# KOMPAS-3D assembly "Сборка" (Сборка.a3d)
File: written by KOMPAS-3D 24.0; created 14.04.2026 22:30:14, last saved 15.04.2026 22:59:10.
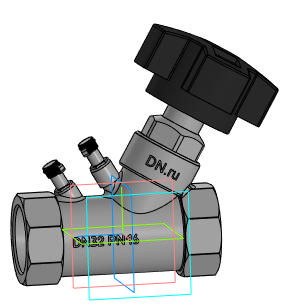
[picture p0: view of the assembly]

Document properties: Автор: tyuri; Полное имя файла: D:\Аутсорс\VB0000P-T Клапан балансировочный статический DN.ru\DN32\Исходные данные\Сборка.a3d

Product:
- Component [detail]: Деталь1  | qty 1  | Автор: tyuri; additional columns: Типовые; source file: Деталь1 - Деталь1.m3d
- Body: Тело 1  | qty 1
    Масса: 0.889548
- Component [detail]: Ручка  | designation Деталь2  | qty 1  | Масса: 0.541971; Автор: tyuri; additional columns: Типовые; source file: Деталь2 - Деталь2.m3d
- Part/product: Сборка
    Масса: 1.431518

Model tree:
1. Эскиз:2  (labels: Грань.Твердое тело1; Ребро.Твердое тело1)
2. Элемент вращения:1  (labels: Грань.Твердое тело1)
     Угол 1 = 360
3. Смещенная плоскость:1
     Расстояние = 40
4. Эскиз:3
5. Элемент выдавливания:1  (with: Грань.Элемент вращения:1)
     Расстояние 1 = -22.4125; Смещение 1 = 0.01
6. Эскиз:4
7. Элемент выдавливания:2  (with: Грань.Элемент вращения:1)  (labels: Грань.Твердое тело1; Ребро.Твердое тело1; Твердое тело1)
     Расстояние 1 = -21.0012; Смещение 1 = 0.001; Ориентация = 2; Расстояние = 7

Referenced files in D:\Аутсорс\VB0000P-T Клапан балансировочный статический DN.ru\DN32\Исходные данные\: Деталь1 - Деталь1.m3d, Деталь2 - Деталь2.m3d
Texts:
  DN32 PN16
  GOST 26.020 Pr3
  Деталь1 Деталь1
  Деталь2 Ручка
  Ось X.Начало координат
  Ось Z.Начало координат
  Плоскость ZY.Начало координат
